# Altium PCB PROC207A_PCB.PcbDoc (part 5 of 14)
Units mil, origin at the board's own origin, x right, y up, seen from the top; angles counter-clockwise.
Board outline 4094.49 x 3724.79 mil, 8 copper layers (Top Layer, L2_GND1, L3_SIG1, L4_PWR1, L5_PWR2, L6_SIG2, L7_GND2, Bottom Layer), stack 58.1 mil thick; 584 components, 399 nets, 8440 pads, 5258 vias.
Unrouted connection lines stored in the file: 9.
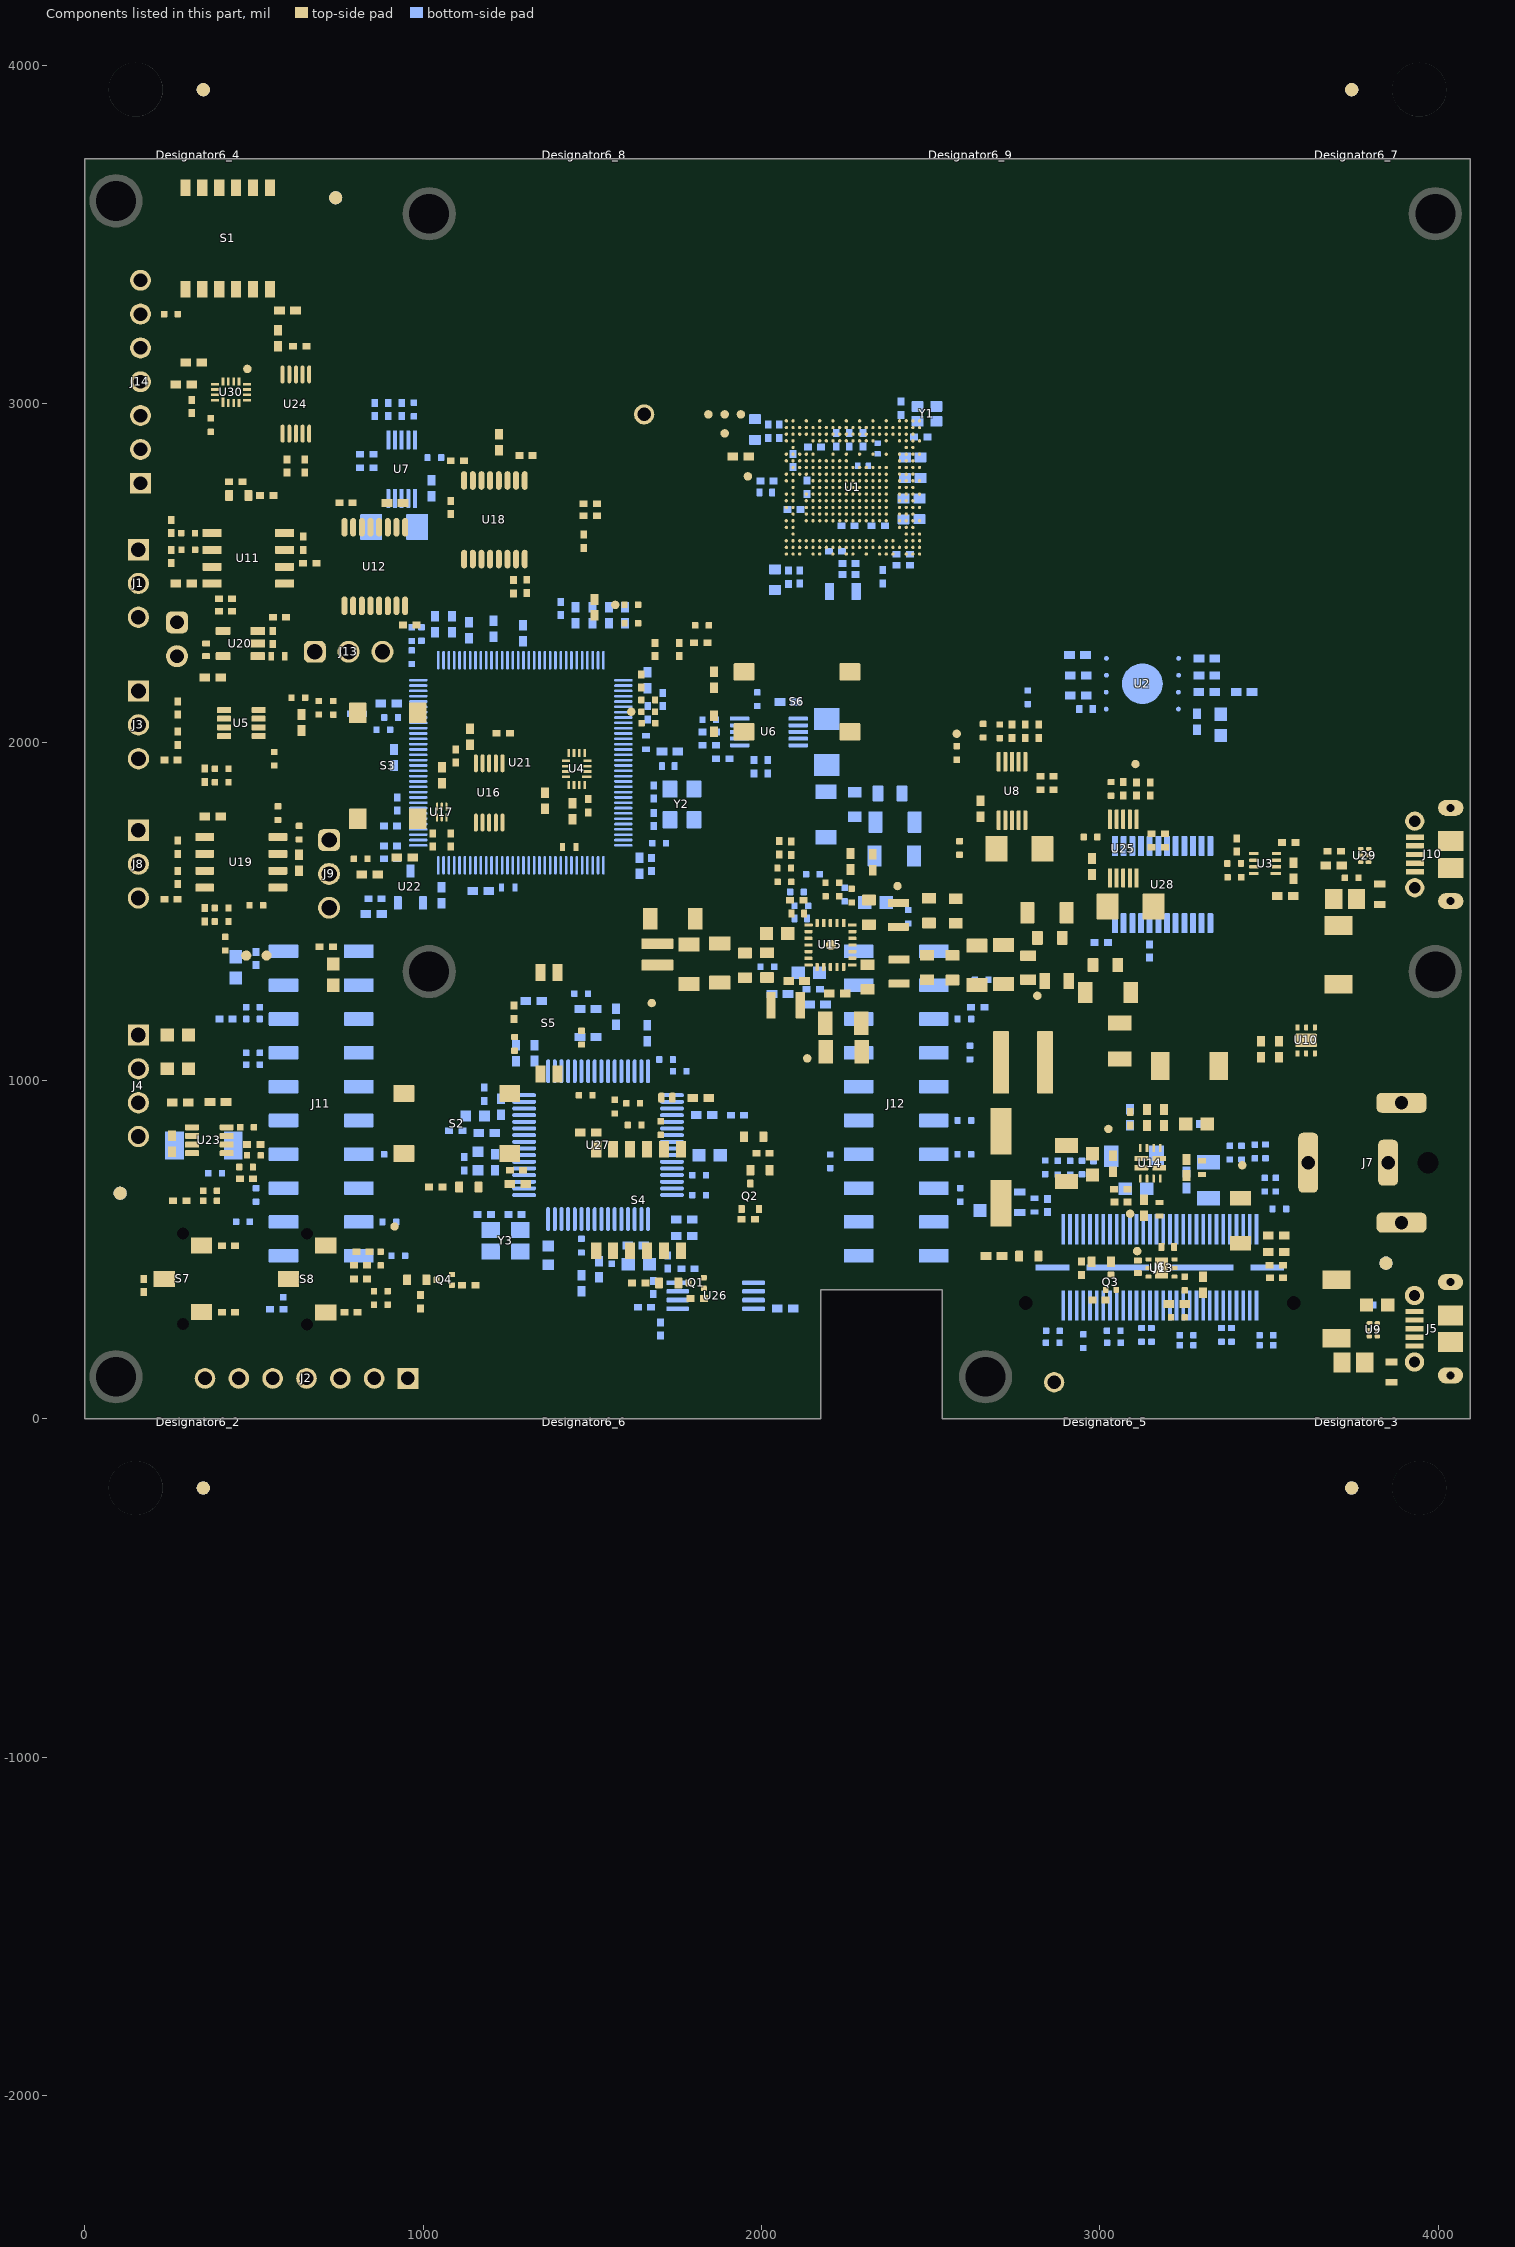
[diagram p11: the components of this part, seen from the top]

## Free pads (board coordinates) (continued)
  round 6 on Mech16: 1(433.25,767.31) 1(433.25,767.31) 1(433.25,798.8) 1(433.25,798.8) 1(437.27,664.31) 1(437.27,664.31) 1(437.27,695.8) 1(437.27,695.8) 1(446.26,465.31) 1(446.26,465.31) 1(446.26,496.8) 1(446.26,496.8) 1(448.26,567.31) 1(448.26,567.31) 1(448.26,598.8) 1(448.26,598.8) 1(453.78,767.31) 1(453.78,798.8) 1(457.79,664.31) 1(457.79,695.8) 1(466.79,465.31) 1(466.79,496.8) 1(468.79,567.31) 1(468.79,598.8) 1(471.78,767.31) 1(471.78,798.8) 1(475.79,664.31) 1(475.79,695.8) 1(478.32,-915.47) 1(479.32,-865.47) 1(481.32,-863.47) 1(481.32,-863.47) 1(481.32,-815.47) 1(481.32,-815.47) 1(484.79,465.31) 1(484.79,496.8) 1(486.79,567.31) 1(486.79,598.8) 1(492.31,767.31) 1(492.31,767.31) 1(492.31,798.8) 1(492.31,798.8) 1(492.32,-915.47) 1(492.32,-915.47) 1(492.32,-804.47) 1(496.32,664.31) 1(496.32,664.31) 1(496.32,695.8) 1(496.32,695.8) 1(505.31,465.31) 1(505.31,465.31) 1(505.31,496.8) 1(505.31,496.8) 1(507.31,567.31) 1(507.31,567.31) 1(507.31,598.8) 1(507.31,598.8) 1(507.32,-900.47) 1(558.04,-34.47) 1(558.04,-34.47) 1(558.04,-13.94) 1(558.04,4.06) 1(558.04,24.59) 1(558.04,24.59) 1(561.32,-56.47) 1(589.53,-34.47) 1(589.53,-34.47) 1(589.53,-13.94) 1(589.53,4.06) 1(589.53,24.59) 1(589.53,24.59) 1(593.32,-56.47) 1(593.32,-56.47) 1(594.32,-55.47) 1(662.41,-202.87) 1(662.41,-202.87) 1(662.41,-182.34) 1(662.41,-164.34) 1(662.41,-143.81) 1(662.41,-143.81) 1(662.41,-132.87) 1(662.41,-132.87) 1(662.41,-112.34) 1(662.41,-94.34) 1(662.41,-73.81) 1(662.41,-73.81) 1(693.9,-202.87) 1(693.9,-202.87) 1(693.9,-182.34) 1(693.9,-164.34) 1(693.9,-143.81) 1(693.9,-143.81) 1(693.9,-132.87) 1(693.9,-132.87) 1(693.9,-112.34) 1(693.9,-94.34) 1(693.9,-73.81) 1(693.9,-73.81) 1(787.16,1515.96) 1(787.16,1515.96) 1(787.16,2008) 1(787.16,2008) 1(794.6,1523.56) 1(794.6,1523.56) 1(794.6,1697.96) 1(794.6,1697.96) 1(794.68,1523.48) 1(794.68,1523.48) 1(794.68,1697.92) 1(794.68,1697.92) 1(833.52,1958.52) 1(833.52,1958.52) 1(835.4,1965.36) 1(835.4,1965.36) 1(835.52,1949.8) 1(835.52,1949.8) 1(835.56,1965.6) 1(835.56,1965.6) 1(835.64,1579.88) 1(835.64,1579.88) 1(835.64,1596.8) 1(835.64,1596.8) 1(837.76,1579.88) 1(837.76,1579.88) 1(837.76,1593.92) 1(837.76,1593.92) 1(837.84,1593.92) 1(837.84,1593.92) 1(838.72,1596.8) 1(838.72,1596.8) 1(839,1957.24) 1(839,1957.24) 1(839.88,1962.4) 1(839.88,1962.4) 1(839.96,1962.56) 1(839.96,1962.56) 1(840.48,1951.8) 1(840.48,1951.8) 1(841.2,1969.8) 1(841.2,1969.8) 1(843.12,1579.88) 1(843.12,1579.88) 1(844.08,1582.56) 1(844.08,1582.56) 1(844.4,1965.2) 1(844.4,1965.2) 1(845,1579.88) 1(845,1579.88) 1(845.16,1943.08) 1(845.16,1943.08) 1(847.48,1930.88) 1(847.48,1930.88) 1(849.4,1596.8) 1(849.4,1596.8) 1(850.04,1965.8) 1(850.04,1965.8) 1(850.08,1971.16) 1(850.08,1971.16) 1(850.32,1593.92) 1(850.32,1593.92) 1(850.36,1579.88) 1(850.36,1579.88) 1(850.36,1593.92) 1(850.36,1593.92) 1(852.48,1579.88) 1(852.48,1579.88) 1(852.48,1596.8) 1(852.48,1596.8) 1(852.52,1933.12) 1(852.52,1933.12) 1(854.36,1594.88) 1(854.36,1594.88) 1(854.36,1596.8) 1(854.36,1596.8) 1(860.04,1579.88) 1(860.04,1579.88) 1(860.04,1594.88) 1(860.04,1594.88) 1(860.04,1964.6) 1(860.04,1964.6) 1(860.16,1970.04) 1(860.16,1970.04) 1(862.24,1922.32) 1(862.24,1922.32) 1(862.28,1579.88) 1(862.28,1579.88) 1(862.28,1594.88) 1(862.28,1594.88) 1(867.92,1594.88) 1(867.92,1594.88) 1(867.92,1596.8) 1(867.92,1596.8) 1(868,1909.28) 1(868,1909.28) 1(868.56,1626.32) 1(868.56,1626.32) 1(868.56,1646.72) 1(868.56,1646.72) 1(869.32,1651.12) 1(869.32,1651.12) 1(870.6,1557.36) 1(870.6,1557.36) 1(870.6,1598.36) 1(870.6,1598.36) 1(871.44,1654.28) 1(871.44,1654.28) 1(872.04,1966.96) 1(872.04,1966.96) 1(872.16,1961.32) 1(872.16,1961.32) 1(874.08,1910.96) 1(874.08,1910.96) 1(874.72,1656.2) 1(874.72,1656.2) 1(875.12,1626.32) 1(875.12,1626.32) 1(875.12,1645) 1(875.12,1645) 1(876.64,1650.08) 1(876.64,1650.08) 1(877.72,1922.28) 1(877.72,1922.28) 1(878.2,1557.36) 1(878.2,1557.36) 1(878.2,1560.6) 1(878.2,1560.6) 1(878.32,1560.6) 1(878.32,1560.6) 1(878.52,1572.8) 1(878.52,1572.8) 1(878.52,1585.4) 1(878.52,1585.4) 1(878.52,1598.36) 1(878.52,1598.36) 1(878.62,-1419.4) 1(878.64,1585.4) 1(878.64,1585.4) 1(878.72,1568.4) 1(878.72,1568.4) 1(878.72,1577.24) 1(878.72,1577.24) 1(879.12,1656.84) 1(879.12,1656.84) 1(879.32,1565.2) 1(879.32,1565.2) 1(879.32,1580.4) 1(879.32,1580.4) 1(880.6,1563.28) 1(880.6,1563.28) 1(880.6,1582.32) 1(880.6,1582.32) 1(880.92,1651.68) 1(880.92,1651.68) 1(881.32,1557.52) 1(881.32,1557.52) 1(881.48,1588.16) 1(881.48,1588.16) 1(882.76,1562.64) 1(882.76,1562.64) 1(882.76,1582.96) 1(882.76,1582.96) 1(883.92,1651.08) 1(883.92,1651.08) 1(884.12,1933.44) 1(884.12,1933.44) 1(884.4,1655.52) 1(884.4,1655.52) 1(884.84,1563.28) 1(884.84,1563.28) 1(884.84,1582.32) 1(884.84,1582.32) 1(885.32,1556.52) 1(885.32,1556.52) 1(885.32,1589.04) 1(885.32,1589.04) 1(885.36,1962.16) 1(885.36,1962.16) 1(886,1956.12) 1(886,1956.12) 1(886.12,1565.2) 1(886.12,1565.2) 1(886.12,1580.4) 1(886.12,1580.4) 1(886.16,1649.4) 1(886.16,1649.4) 1(886.72,1568.36) 1(886.72,1568.36) 1(886.72,1577.24) 1(886.72,1577.24) 1(886.88,1572.8) 1(886.88,1572.8) 1(887.6,1646.92) 1(887.6,1646.92) 1(887.79,-1434) 1(887.79,-1428.57) 1(887.79,-1428.57) 1(888,1652.12) 1(888,1652.12) 1(888.12,1626.32) 1(888.12,1626.32) 1(888.12,1643.84) 1(888.12,1643.84) 1(888.12,1652.12) 1(888.12,1652.12) 1(888.12,1667.36) 1(888.12,1667.36) 1(889.56,1557.44) 1(889.56,1557.44) 1(889.56,1588.12) 1(889.56,1588.12) 1(892.28,1942.92) 1(892.28,1942.92) 1(892.52,1560.36) 1(892.52,1560.36) 1(892.52,1585.24) 1(892.52,1585.24) 1(894.24,1565.4) 1(894.24,1565.4) 1(894.24,1580.2) 1(894.24,1580.2) 1(894.32,1887.44) 1(894.32,1887.44) 1(894.68,1626.32) 1(894.68,1626.32) 1(894.68,1667.36) 1(894.68,1667.36) 1(894.8,1572.8) 1(894.8,1572.8) 1(899.32,1557.36) 1(899.32,1557.36) 1(899.68,1955.8) 1(899.68,1955.8) 1(899.92,1626.36) 1(899.92,1626.36) 1(899.92,1631.44) 1(899.92,1631.44) 1(899.92,1651.16) 1(899.92,1651.16) 1(899.92,1656.04) 1(899.92,1656.04) 1(900.08,1559.92) 1(900.08,1559.92) 1(900.28,1563.32) 1(900.28,1563.32) 1(900.28,1579.6) 1(900.28,1579.6) 1(900.68,1583.4) 1(900.68,1583.4) 1(901.12,1949.16) 1(901.12,1949.16) 1(902.36,1586.4) 1(902.36,1586.4) 1(902.68,1631.2) 1(902.68,1631.2) 1(904.16,1626.04) 1(904.16,1626.04) 1(905.36,1632.24) 1(905.36,1632.24) 1(905.76,1588.36) 1(905.76,1588.36) 1(905.84,1635.28) 1(905.84,1635.28) 1(905.84,1651.16) 1(905.84,1651.16) 1(905.84,1656.04) 1(905.84,1656.04) 1(905.84,1664.96) 1(905.84,1664.96) 1(906.88,1557.36) 1(906.88,1557.36) 1(907.88,1560.56) 1(907.88,1560.56) 1(907.88,1566.72) 1(907.88,1566.72) 1(907.88,1572.8) 1(907.88,1572.8) 1(907.88,1579.88) 1(907.88,1579.88) 1(907.96,1560.56) 1(907.96,1560.56) 1(908.32,1626.52) 1(908.32,1626.52) 1(908.56,1577.52) 1(908.56,1577.52) 1(908.72,1582.64) 1(908.72,1582.64) 1(909.52,1563.04) 1(909.52,1563.04) 1(910.8,1628) 1(910.8,1628) 1(910.96,1882.16) 1(910.96,1882.16) 1(911,1576.24) 1(911,1576.24) 1(911.16,1557.36) 1(911.16,1557.36) 1(911.24,1571.24) 1(911.24,1571.24) 1(911.48,1589.04) 1(911.48,1589.04) 1(911.52,1583.64) 1(911.52,1583.64) 1(912,1630.36) 1(912,1630.36) 1(912.36,1633.64) 1(912.36,1633.64) 1(912.36,1651.16) 1(912.36,1651.16) 1(912.36,1656.04) 1(912.36,1656.04) 1(912.36,1664.96) 1(912.36,1664.96) 1(912.76,1561.92) 1(912.76,1561.92) 1(914.28,1582.56) 1(914.28,1582.56) 1(914.28,1895.2) 1(914.28,1895.2) 1(914.56,1948.12) 1(914.56,1948.12) 1(914.72,1569.52) 1(914.72,1569.52) 1(915.04,1563.2) 1(915.04,1563.2) 1(915.2,1578.8) 1(915.2,1578.8) 1(915.2,1579.64) 1(915.2,1579.64) 1(915.52,1575.04) 1(915.52,1575.04) 1(915.72,1566.24) 1(915.72,1566.24) 1(915.72,1588.56) 1(915.72,1588.56) 1(915.84,1556.52) 1(915.84,1556.52) 1(917.32,1651.16) 1(917.32,1651.16) 1(917.32,1656.04) 1(917.32,1656.04) 1(919.04,1573.72) 1(919.04,1573.72) 1(919.16,1586.96) 1(919.16,1586.96) 1(919.36,1557.32) 1(919.36,1557.32) 1(921.44,1571.84) 1(921.44,1571.84) 1(921.48,1584.04) 1(921.48,1584.04) 1(921.64,1559.4) 1(921.64,1559.4) 1(921.64,1908.32) 1(921.64,1908.32) 1(921.96,1626.32) 1(921.96,1626.32) 1(921.96,1656.04) 1(921.96,1656.04) 1(921.96,1661.16) 1(921.96,1661.16) 1(921.96,1667.36) 1(921.96,1667.36) 1(922.32,1578.8) 1(922.32,1578.8) 1(922.32,1579.52) 1(922.32,1579.52) 1(922.88,1569.12) 1(922.88,1569.12) 1(922.92,1562.28) 1(922.92,1562.28) 1(923.32,-48.23) 1(923.32,-48.23) 1(923.32,-39.47) 1(923.32,1565.4) 1(923.32,1565.4) 1(923.64,1867.84) 1(923.64,1867.84) 1(924.24,1586.08) 1(924.24,1586.08) 1(924.84,1590.6) 1(924.84,1590.6) 1(925.2,1580.56) 1(925.2,1580.56) 1(926.72,1594.52) 1(926.72,1594.52) 1(927.68,1865.48) 1(927.68,1865.48) 1(927.84,1576.72) 1(927.84,1576.72) 1(928.52,1626.32) 1(928.52,1626.32) 1(928.52,1656.04) 1(928.52,1656.04) 1(928.52,1661.16) 1(928.52,1661.16) 1(928.52,1667.36) 1(928.52,1667.36) 1(929.64,1939.36) 1(929.64,1939.36) 1(930.2,1597.32) 1(930.2,1597.32) 1(930.41,-55.32) 1(930.56,1846.16) 1(930.56,1846.16) 1(931.36,1919.08) 1(931.36,1919.08) 1(931.96,1574.48) 1(931.96,1574.48) 1(932.52,1585.96) 1(932.52,1585.96) 1(933.44,1656.04) 1(933.44,1656.04) 1(933.52,1892.56) 1(933.52,1892.56) 1(933.84,1590.64) 1(933.84,1590.64) 1(934.04,1581.32) 1(934.04,1581.32) 1(934.68,1846.84) 1(934.68,1846.84) 1(935.4,651.01) 1(935.4,651.01) 1(935.4,651.01) 1(935.52,1598.36) 1(935.52,1598.36) 1(937.28,1573.72) 1(937.28,1573.72) 1(938.04,1579.8) 1(938.04,1579.8) 1(938.28,1592.28) 1(938.28,1592.28) 1(939.32,1901.08) 1(939.32,1901.08) 1(940.08,1656.04) 1(940.08,1656.04) 1(941.08,1925.6) 1(941.08,1925.6) 1(941.72,1557.36) 1(941.72,1557.36) 1(941.72,1573.72) 1(941.72,1573.72) 1(941.72,1579.8) 1(941.72,1579.8) 1(941.72,1592.28) 1(941.72,1592.28) 1(941.76,1925.04) 1(941.76,1925.04) 1(942.72,1626.32) 1(942.72,1626.32) 1(943.72,1863) 1(943.72,1863) 1(943.9,642.51) 1(943.9,642.51) 1(943.9,659.51) 1(943.9,659.51) 1(944.44,1929.68) 1(944.44,1929.68) 1(945.96,1828.64) 1(945.96,1828.64) 1(946.12,1633.84) 1(946.12,1633.84) 1(946.24,1633.84) 1(946.24,1633.84) 1(946.42,-1436) 1(946.42,-1425) 1(946.42,-1425) 1(946.42,-1425) 1(949.32,1854.56) 1(949.32,1854.56) 1(949.44,1626.32) 1(949.44,1626.32) 1(950,1557.36) 1(950,1557.36) 1(950,1598.36) 1(950,1598.36) 1(951.24,1829.24) 1(951.24,1829.24) 1(951.6,1656.04) 1(951.6,1656.04) 1(954.96,1648.4) 1(954.96,1648.4) 1(955.08,1648.4) 1(955.08,1648.4) 1(957.2,1557.36) 1(957.2,1557.36) 1(957.2,1580.28) 1(957.2,1580.28) 1(957.72,1584.2) 1(957.72,1584.2) 1(958.2,1656.04) 1(958.2,1656.04) 1(958.64,1919.32) 1(958.64,1919.32) 1(959.28,1586.96) 1(959.28,1586.96) 1(960.56,1626.32) 1(960.56,1626.32) 1(961.76,1588.56) 1(961.76,1588.56) 1(962.32,1916.44) 1(962.32,1916.44) 1(963.44,1820.72) 1(963.44,1820.72) 1(963.76,1633.84) 1(963.76,1633.84) 1(963.88,1633.84) 1(963.88,1633.84) 1(965.08,1589.04) 1(965.08,1589.04) 1(965.12,1557.36) 1(965.12,1557.36) 1(965.12,1578.64) 1(965.12,1578.64) 1(965.2,1815.24) 1(965.2,1815.24) 1(965.36,1834.68) 1(965.36,1834.68) 1(965.92,1581.96) 1(965.92,1581.96) 1(966.16,1840.92) 1(966.16,1840.92) 1(966.6,1828.96) 1(966.6,1828.96) 1(967.44,1626.32) 1(967.44,1626.32) 1(968.52,1582.96) 1(968.52,1582.96) 1(969.2,1834.84) 1(969.2,1834.84) 1(969.24,1824.2) 1(969.24,1824.2) 1(969.52,1588.08) 1(969.52,1588.08) 1(969.68,1656.04) 1(969.68,1656.04) 1(969.72,1847.16) 1(969.72,1847.16) 1(969.76,1847.2) 1(969.76,1847.2) 1(969.84,1839.8) 1(969.84,1839.8) 1(969.96,1921.52) 1(969.96,1921.52) 1(970.2,1830.28) 1(970.2,1830.28) 1(970.68,1822.24) 1(970.68,1822.24) 1(970.72,1902.32) 1(970.72,1902.32) 1(971.64,1581.72) 1(971.64,1581.72) 1(972.28,1826.48) 1(972.28,1826.48) 1(972.6,1585.12) 1(972.6,1585.12) 1(972.68,1844.72) 1(972.68,1844.72) 1(972.72,1557.36) 1(972.72,1557.36) 1(972.72,1577.84) 1(972.72,1577.84) 1(972.72,1585.12) 1(972.72,1585.12) 1(972.72,1598.36) 1(972.72,1598.36) 1(972.8,1844.88) 1(972.8,1844.88) 1(972.96,1851.92) 1(972.96,1851.92) 1(973.76,1818.04) 1(973.76,1818.04) 1(973.76,1824.48) 1(973.76,1824.48) 1(976.64,1656.04) 1(976.64,1656.04) 1(977.64,1812.96) 1(977.64,1812.96) 1(979.04,1817.4) 1(979.04,1817.4) 1(980,1862.24) 1(980,1862.24) 1(980.48,1900.36) 1(980.48,1900.36) 1(980.64,1557.36) 1(980.64,1557.36) 1(980.64,1598.36) 1(980.64,1598.36) 1(981.36,1920.88) 1(981.36,1920.88) 1(982.24,1916.76) 1(982.24,1916.76) 1(983.2,1860.16) 1(983.2,1860.16) 1(983.64,1805.96) 1(983.64,1805.96) 1(984.6,1869.04) 1(984.6,1869.04) 1(985.32,1569.16) 1(985.32,1569.16) 1(985.32,1577.12) 1(985.32,1577.12) 1(985.84,1809) 1(985.84,1809) 1(985.96,1563.8) 1(985.96,1563.8) 1(986,1582.04) 1(986,1582.04) 1(987.72,1866.8) 1(987.72,1866.8) 1(988.04,1559.8) 1(988.04,1559.8) 1(988.12,1585.8) 1(988.12,1585.8) 1(988.4,1837.72) 1(988.4,1837.72) 1(991.52,1839.92) 1(991.52,1839.92) 1(991.56,1588.2) 1(991.56,1588.2) 1(991.56,1879.32) 1(991.56,1879.32) 1(991.68,1557.36) 1(991.68,1557.36) 1(992.52,1917.84) 1(992.52,1917.84) 1(992.88,1569.16) 1(992.88,1569.16) 1(992.88,1577.12) 1(992.88,1577.12) 1(993.56,1581.32) 1(993.56,1581.32) 1(993.8,1563.68) 1(993.8,1563.68) 1(994.8,1884) 1(994.8,1884) 1(994.84,1884.04) 1(994.84,1884.04) 1(995.96,1635.16) 1(995.96,1635.16) 1(996.36,1589.04) 1(996.36,1589.04) 1(996.44,1583.32) 1(996.44,1583.32) 1(996.72,1561.92) 1(996.72,1561.92) 1(996.8,1638.84) 1(996.8,1638.84) 1(996.96,1647.72) 1(996.96,1647.72) 1(997.08,1556.52) 1(997.08,1556.52) 1(997.2,1630.68) 1(997.2,1630.68) 1(998.16,1882.2) 1(998.16,1882.2) 1(998.36,1651.92) 1(998.36,1651.92) 1(998.8,1582.68) 1(998.8,1582.68) 1(998.92,1562.56) 1(998.92,1562.56) 1(999,1641.32) 1(999,1641.32) 1(999.32,1889.68) 1(999.32,1889.68) 1(1000.2,1564.48) 1(1000.2,1564.48) 1(1000.2,1580.72) 1(1000.2,1580.72) 1(1000.28,1627.72) 1(1000.28,1627.72) 1(1000.84,1567.84) 1(1000.84,1567.84) 1(1000.84,1577.4) 1(1000.84,1577.4) 1(1001,1572.72) 1(1001,1572.72) 1(1001.16,1654.76) 1(1001.16,1654.76) 1(1001.44,1588.32) 1(1001.44,1588.32) 1(1001.72,1886.68) 1(1001.72,1886.68) 1(1002.04,1642.88) 1(1002.04,1642.88) 1(1002.28,1557.32) 1(1002.28,1557.32) 1(1002.52,1634.6) 1(1002.52,1634.6) 1(1003.12,1632.56) 1(1003.12,1632.56) 1(1003.32,1913) 1(1003.32,1913) 1(1003.44,1636.68) 1(1003.44,1636.68) 1(1003.76,1647.72) 1(1003.76,1647.72) 1(1003.84,1862.88) 1(1003.84,1862.88) 1(1004.08,1862.76) 1(1004.08,1862.76) 1(1004.6,1626.04) 1(1004.6,1626.04) 1(1004.68,1907.84) 1(1004.68,1907.84) 1(1004.8,1892.72) 1(1004.8,1892.72) 1(1004.84,1631.4) 1(1004.84,1631.4) 1(1004.96,1656.36) 1(1004.96,1656.36) 1(1005.28,1821.6) 1(1005.28,1821.6) 1(1005.36,1866.36) 1(1005.36,1866.36) 1(1005.4,1585.68) 1(1005.4,1585.68) 1(1005.56,1643.84) 1(1005.56,1643.84) 1(1005.56,1866.28) 1(1005.56,1866.28) 1(1005.64,1637.96) 1(1005.64,1637.96) 1(1005.92,1650.84) 1(1005.92,1650.84) 1(1005.96,1560) 1(1005.96,1560) 1(1006.08,1889.08) 1(1006.08,1889.08) 1(1007.04,1630.84) 1(1007.04,1630.84) 1(1008,1580.68) 1(1008,1580.68) 1(1008.2,1565.04) 1(1008.2,1565.04) 1(1008.72,1638.8) 1(1008.72,1638.8) 1(1008.92,1572.8) 1(1008.92,1572.8) 1(1009.12,1630.68) 1(1009.12,1630.68) 1(1009.12,1644.6) 1(1009.12,1644.6) 1(1009.24,1625.52) 1(1009.24,1625.52) 1(1009.36,1656.84) 1(1009.36,1656.84) 1(1009.8,1651.68) 1(1009.8,1651.68) 1(1009.88,1842.8) 1(1009.88,1842.8) 1(1010.6,1893.64) 1(1010.6,1893.64) 1(1010.72,1889.84) 1(1010.72,1889.84) 1(1012.2,1645.44) 1(1012.2,1645.44) 1(1012.24,1639.56) 1(1012.24,1639.56) 1(1012.92,1835.4) 1(1012.92,1835.4) 1(1013.24,1651.12) 1(1013.24,1651.12) 1(1013.48,1906.88) 1(1013.48,1906.88) 1(1013.56,1656.44) 1(1013.56,1656.44) 1(1013.6,1557.36) 1(1013.6,1557.36) 1(1013.6,1580.28) 1(1013.6,1580.28) 1(1013.68,1631.84) 1(1013.68,1631.84) 1(1013.72,1848.4) 1(1013.72,1848.4) 1(1014.12,1584.2) 1(1014.12,1584.2) 1(1014.4,1646.68) 1(1014.4,1646.68) 1(1014.44,1626.16) 1(1014.44,1626.16) 1(1015,1889.24) 1(1015,1889.24) 1(1015.2,1648.64) 1(1015.2,1648.64) 1(1015.68,1586.96) 1(1015.68,1586.96) 1(1015.76,1640.52) 1(1015.76,1640.52) 1(1015.84,1635.84) 1(1015.84,1635.84) 1(1015.84,1635.88) 1(1015.84,1635.88) 1(1015.92,1837.76) 1(1015.92,1837.76) 1(1016,1892.96) 1(1016,1892.96) 1(1016.52,1802.72) 1(1016.52,1802.72) 1(1017.08,1899.64) 1(1017.08,1899.64) 1(1017.36,1857) 1(1017.36,1857) 1(1017.4,1888.64) 1(1017.4,1888.64) 1(1017.6,1655.04) 1(1017.6,1655.04) 1(1018.12,1588.56) 1(1018.12,1588.56) 1(1018.36,1892.36) 1(1018.36,1892.36) 1(1018.6,1628.08) 1(1018.6,1628.08) 1(1018.8,1642.08) 1(1018.8,1642.08) 1(1018.96,1860.48) 1(1018.96,1860.48) 1(1019.48,1805.32) 1(1019.48,1805.32) 1(1020.6,1652.4) 1(1020.6,1652.4) 1(1020.96,1644.56) 1(1020.96,1644.56) 1(1021.36,1631.28) 1(1021.36,1631.28) 1(1021.44,1589.04) 1(1021.44,1589.04) 1(1021.52,1557.36) 1(1021.52,1557.36) 1(1021.52,1578.64) 1(1021.52,1578.64) 1(1021.76,1648.32) 1(1021.76,1648.32) 1(1022.32,1581.96) 1(1022.32,1581.96) 1(1022.44,1635.88) 1(1022.44,1635.88) 1(1022.84,1900.04) 1(1022.84,1900.04) 1(1023.4,1891) 1(1023.4,1891) 1(1024.52,1626.32) 1(1024.52,1626.32) 1(1024.92,1582.96) 1(1024.92,1582.96) 1(1025.64,1656.04) 1(1025.64,1656.04) 1(1025.92,1886.32) 1(1025.92,1886.32) 1(1026,1588) 1(1026,1588) 1(1028,1581.72) 1(1028,1581.72) 1(1029.12,1557.36) 1(1029.12,1557.36) 1(1029.12,1577.84) 1(1029.12,1577.84) 1(1029.32,1584.64) 1(1029.32,1584.64) 1(1029.44,1584.64) 1(1029.44,1584.64) 1(1029.44,1588.24) 1(1029.44,1588.24) 1(1029.44,1817) 1(1029.44,1817) 1(1029.52,1889.28) 1(1029.52,1889.28) 1(1031.16,1892.96) 1(1031.16,1892.96) 1(1032.16,1819.72) 1(1032.16,1819.72) 1(1032.4,1850.04) 1(1032.4,1850.04) 1(1032.52,1626.32) 1(1032.52,1626.32) 1(1032.64,1864.12) 1(1032.64,1864.12) 1(1033.32,1867.84) 1(1033.32,1867.84) 1(1033.68,1656.04) 1(1033.68,1656.04) 1(1034.16,1853.44) 1(1034.16,1853.44) 1(1034.44,1790.88) 1(1034.44,1790.88) 1(1036.24,1883.08) 1(1036.24,1883.08) 1(1037,1645.12) 1(1037,1645.12) 1(1037.04,1557.36) 1(1037.04,1557.36) 1(1037.04,1588.24) 1(1037.04,1588.24) 1(1038.2,1886.28) 1(1038.2,1886.28) 1(1041.6,1640.76) 1(1041.6,1640.76) 1(1042.84,1557.36) 1(1042.84,1557.36) 1(1042.84,1588.24) 1(1042.84,1588.24) 1(1045.52,1626.32) 1(1045.52,1626.32) 1(1045.52,1636.96) 1(1045.52,1636.96) 1(1045.52,1644.04) 1(1045.52,1644.04) 1(1045.52,1667.36) 1(1045.52,1667.36) 1(1046.44,1776.08) 1(1046.44,1776.08) 1(1048.36,1800.72) 1(1048.36,1800.72) 1(1048.88,1841.56) 1(1048.88,1841.56) 1(1050.4,1557.36) 1(1050.4,1557.36) 1(1050.4,1560.96) 1(1050.4,1560.96) 1(1050.4,1778.04) 1(1050.4,1778.04) 1(1050.52,1560.96) 1(1050.52,1560.96) 1(1050.6,1858.96) 1(1050.6,1858.96) 1(1050.76,1567.72) 1(1050.76,1567.72) 1(1050.76,1588.24) 1(1050.76,1588.24) 1(1050.76,1803.72) 1(1050.76,1803.72) 1(1050.8,1844.88) 1(1050.8,1844.88) 1(1051.76,1862.6) 1(1051.76,1862.6) 1(1051.84,1563.88) 1(1051.84,1563.88) 1(1052.04,1667.36) 1(1052.04,1667.36) 1(1052.08,1626.32) 1(1052.08,1626.32) 1(1052.08,1667.36) 1(1052.08,1667.36) 1(1053.84,1557.6) 1(1053.84,1557.6) 1(1054.96,1562.64) 1(1054.96,1562.64) 1(1055.64,1650.36) 1(1055.64,1650.36) 1(1055.64,1656.68) 1(1055.64,1656.68) 1(1057.44,651.01) 1(1057.56,1563.64) 1(1057.56,1563.64) 1(1058.08,1656.84) 1(1058.08,1656.84) 1(1058.36,1566.92) 1(1058.36,1566.92) 1(1058.36,1588.24) 1(1058.36,1588.24) 1(1058.4,1556.52) 1(1058.4,1556.52) 1(1058.44,1650.64) 1(1058.44,1650.64) 1(1061.08,1656.28) 1(1061.08,1656.28) 1(1061.6,1649.96) 1(1061.6,1649.96) 1(1061.72,1557.04) 1(1061.72,1557.04) 1(1063.68,1654.76) 1(1063.68,1654.76) 1(1064.16,1648) 1(1064.16,1648) 1(1064.2,1558.64) 1(1064.2,1558.64) 1(1064.4,1764.08) 1(1064.4,1764.08) 1(1065.68,1652.64) 1(1065.68,1652.64) 1(1065.76,1561.4) 1(1065.76,1561.4) 1(1065.88,1644.84) 1(1065.88,1644.84) 1(1066.28,1565.32) 1(1066.28,1565.32) 1(1066.28,1588.24) 1(1066.28,1588.24) 1(1066.48,1626.32) 1(1066.48,1626.32) 1(1066.48,1640.48) 1(1066.48,1640.48) 1(1066.52,1831.28) 1(1066.52,1831.28) 1(1066.8,1650.28) 1(1066.8,1650.28) 1(1066.88,1650.28) 1(1066.88,1650.28) 1(1066.88,1656.04) 1(1066.88,1656.04) 1(1067.68,1766.64) 1(1067.68,1766.64) 1(1068.6,1834.48) 1(1068.6,1834.48) 1(1070.36,1849.96) 1(1070.36,1849.96) 1(1070.52,1785.92) 1(1070.52,1785.92) 1(1071.52,1557.36) 1(1071.52,1557.36) 1(1071.92,1853.44) 1(1071.92,1853.44) 1(1072.32,1559.92) 1(1072.32,1559.92) 1(1072.48,1563.32) 1(1072.48,1563.32) 1(1072.48,1579.6) 1(1072.48,1579.6) 1(1072.56,1789.16) 1(1072.56,1789.16) 1(1072.92,1583.4) 1(1072.92,1583.4) 1(1073.04,1626.32) 1(1073.04,1626.32) 1(1073.04,1656.04) 1(1073.04,1656.04) 1(1074.56,1586.4) 1(1074.56,1586.4) 1(1078,1588.36) 1(1078,1588.36) 1(1079.12,1557.36) 1(1079.12,1557.36) 1(1079.12,1641.2) 1(1079.12,1641.2) 1(1080.08,1560.56) 1(1080.08,1560.56) 1(1080.08,1566.72) 1(1080.08,1566.72) 1(1080.08,1572.8) 1(1080.08,1572.8) 1(1080.08,1579.88) 1(1080.08,1579.88) 1(1080.12,1634.92) 1(1080.12,1634.92) 1(1080.12,1647.48) 1(1080.12,1647.48) 1(1080.2,1560.56) 1(1080.2,1560.56) 1(1080.8,1577.52) 1(1080.8,1577.52) 1(1080.92,1582.64) 1(1080.92,1582.64) 1(1081.72,1563.04) 1(1081.72,1563.04) 1(1083.04,1629.92) 1(1083.04,1629.92) 1(1083.04,1652.44) 1(1083.04,1652.44) 1(1083.24,1576.24) 1(1083.24,1576.24) 1(1083.4,1557.36) 1(1083.4,1557.36) 1(1083.48,1571.24) 1(1083.48,1571.24) 1(1083.72,1589.04) 1(1083.72,1589.04) 1(1083.76,1583.64) 1(1083.76,1583.64) 1(1084.4,1753.2) 1(1084.4,1753.2) 1(1084.96,1561.92) 1(1084.96,1561.92) 1(1085,1818.88) 1(1085,1818.88) 1(1085.64,1641.2) 1(1085.64,1641.2) 1(1086.12,1637.4) 1(1086.12,1637.4) 1(1086.12,1645) 1(1086.12,1645) 1(1086.52,1582.56) 1(1086.52,1582.56) 1(1086.6,1756.36) 1(1086.6,1756.36) 1(1086.92,1569.52) 1(1086.92,1569.52) 1(1087.28,1563.2) 1(1087.28,1563.2) 1(1087.28,1821.96) 1(1087.28,1821.96) 1(1087.44,1578.8) 1(1087.44,1578.8) 1(1087.44,1579.64) 1(1087.44,1579.64) 1(1087.68,1634) 1(1087.68,1634) 1(1087.68,1648.36) 1(1087.68,1648.36) 1(1087.72,1575.04) 1(1087.72,1575.04) 1(1087.72,1626.68) 1(1087.72,1626.68) 1(1087.72,1655.68) 1(1087.72,1655.68) 1(1087.92,1588.56) 1(1087.92,1588.56) 1(1087.96,1566.24) 1(1087.96,1566.24) 1(1088.08,1556.52) 1(1088.08,1556.52) 1(1090.28,1631.6) 1(1090.28,1631.6) 1(1090.28,1650.76) 1(1090.28,1650.76) 1(1091.2,1837.56) 1(1091.2,1837.56) 1(1091.24,1573.72) 1(1091.24,1573.72) 1(1091.4,1586.96) 1(1091.4,1586.96) 1(1091.6,1557.32) 1(1091.6,1557.32) 1(1093.2,1840.8) 1(1093.2,1840.8) 1(1093.68,1571.84) 1(1093.68,1571.84) 1(1093.72,1584.04) 1(1093.72,1584.04) 1(1093.88,1559.4) 1(1093.88,1559.4) 1(1094.08,1625.52) 1(1094.08,1625.52) 1(1094.08,1630.68) 1(1094.08,1630.68) 1(1094.08,1651.68) 1(1094.08,1651.68) 1(1094.08,1656.84) 1(1094.08,1656.84) 1(1094.56,1578.8) 1(1094.56,1578.8) 1(1094.56,1579.52) 1(1094.56,1579.52) 1(1095.08,1569.12) 1(1095.08,1569.12) 1(1095.16,1562.28) 1(1095.16,1562.28) 1(1095.56,1565.4) 1(1095.56,1565.4) 1(1096.64,1772) 1(1096.64,1772) 1(1097.88,1631.6) 1(1097.88,1631.6) 1(1097.88,1650.76) 1(1097.88,1650.76) 1(1098.32,1775.44) 1(1098.32,1775.44) 1(1098.48,1557.36) 1(1098.48,1557.36) 1(1098.48,1564.12) 1(1098.48,1564.12) 1(1100.44,1626.68) 1(1100.44,1626.68) 1(1100.44,1655.68) 1(1100.44,1655.68) 1(1100.52,1634) 1(1100.52,1634) 1(1100.52,1648.36) 1(1100.52,1648.36) 1(1102.04,1637.4) 1(1102.04,1637.4) 1(1102.04,1645) 1(1102.04,1645) 1(1102.56,1641.2) 1(1102.56,1641.2) 1(1104.04,1804.04) 1(1104.04,1804.04) 1(1105.16,1629.92) 1(1105.16,1629.92) 1(1105.16,1652.44) 1(1105.16,1652.44) 1(1106.52,1806.96) 1(1106.52,1806.96) 1(1106.84,1743.24) 1(1106.84,1743.24) 1(1107.48,1747.12) 1(1107.48,1747.12) 1(1108.08,1634.92) 1(1108.08,1634.92) 1(1108.08,1647.48) 1(1108.08,1647.48) 1(1109.08,1641.2) 1(1109.08,1641.2) 1(1111.12,1667.36) 1(1111.12,1667.36) 1(1112.44,1822.04) 1(1112.44,1822.04) 1(1113.12,1564.12) 1(1113.12,1564.12) 1(1113.12,1598.36) 1(1113.12,1598.36) 1(1114.84,1825.04) 1(1114.84,1825.04) 1(1118.4,1667.36) 1(1118.4,1667.36) 1(1121.4,1557.36) 1(1121.4,1557.36) 1(1121.4,1598.36) 1(1121.4,1598.36) 1(1122.44,1626.32) 1(1122.44,1626.32) 1(1122.76,1756.84) 1(1122.76,1756.84) 1(1123.28,1786.48) 1(1123.28,1786.48) 1(1125.44,1759.48) 1(1125.44,1759.48) 1(1125.96,1789.2) 1(1125.96,1789.2) 1(1126.04,1635.96) 1(1126.04,1635.96) 1(1126.16,1635.96) 1(1126.16,1635.96) 1(1128.16,1746.72) 1(1128.16,1746.72) 1(1129.56,1752.68) 1(1129.56,1752.68) 1(1129.72,1626.32) 1(1129.72,1626.32) 1(1130.56,1738.6) 1(1130.56,1738.6) 1(1132.04,1734.08) 1(1132.04,1734.08) 1(1133.12,1744.4) 1(1133.12,1744.4) 1(1134.2,1667.36) 1(1134.2,1667.36) 1(1134.24,1803.04) 1(1134.24,1803.04) 1(1134.56,1735.88) 1(1134.56,1735.88) 1(1134.6,1733.24) 1(1134.6,1733.24) 1(1137.72,1804.96) 1(1137.72,1804.96) 1(1137.96,1657.68) 1(1137.96,1657.68) 1(1138.08,1657.68) 1(1138.08,1657.68) 1(1140.2,1751.76) 1(1140.2,1751.76) 1(1141.56,1667.36) 1(1141.56,1667.36) 1(1142.4,1557.36) 1(1142.4,1557.36) 1(1142.4,1598.36) 1(1142.4,1598.36) 1(1142.48,1765.84) 1(1142.48,1765.84) 1(1145.2,1745.56) 1(1145.2,1745.56) 1(1145.4,1768.32) 1(1145.4,1768.32) 1(1146.44,1626.32) 1(1146.44,1626.32) 1(1149.84,1635.96) 1(1149.84,1635.96) 1(1149.96,1635.96) 1(1149.96,1635.96) 1(1150.68,1557.36) 1(1150.68,1557.36) 1(1150.68,1598.36) 1(1150.68,1598.36) 1(1153.88,1626.32) 1(1153.88,1626.32) 1(1154.08,1782.24) 1(1154.08,1782.24) 1(1155.16,1591.6) 1(1155.16,1591.6) 1(1155.16,1598.36) 1(1155.16,1598.36) 1(1156.4,1745.56) 1(1156.4,1745.56) 1(1157.36,1667.36) 1(1157.36,1667.36) 1(1158.48,1783) 1(1158.48,1783) 1(1161.52,1739.92) 1(1161.52,1739.92) 1(1164.12,1557.36) 1(1164.12,1557.36) 1(1164.12,1591.6) 1(1164.12,1591.6) 1(1164.68,1667.36) 1(1164.68,1667.36) 1(1171.52,1760.24) 1(1171.52,1760.24) 1(1172.32,1740.84) 1(1172.32,1740.84) 1(1172.4,1557.36) 1(1172.4,1557.36) 1(1172.4,1591.6) 1(1172.4,1591.6) 1(1176.56,1759.72) 1(1176.56,1759.72) 1(1176.84,1735.72) 1(1176.84,1735.72) 1(1181.36,1591.6) 1(1181.36,1591.6) 1(1181.36,1598.36) 1(1181.36,1598.36) 1(1182.76,1114) 1(1182.76,1114) 1(1186.2,1737.44) 1(1186.2,1737.44) 1(1189.56,1001.53) 1(1189.56,1120.8) 1(1189.56,1120.8) 1(1189.56,1732.84) 1(1189.56,1732.84) 1(1189.69,1120.8) 1(1191.6,1735.64) 1(1191.6,1735.64) 1(1193.6,1732) 1(1193.6,1732) 1(1196.49,1114) 1(1196.49,1114) 1(1235.36,1523.56) 1(1235.36,1523.56) 1(1235.36,1697.96) 1(1235.36,1697.96) 1(1235.48,1523.48) 1(1235.48,1523.48) 1(1235.48,1697.92) 1(1235.48,1697.92) 1(1242.96,1515.96) 1(1242.96,1515.96) 1(1242.96,2008) 1(1242.96,2008) 1(1279.42,806.53) 1(1279.42,806.53) 1(1286.95,799) 1(1287.79,799) 1(1287.79,799) 1(1287.79,949) 1(1295.32,806.53) 1(1295.32,806.53) 1(1305.8,-2261) 1(1305.8,-2261) 1(1305.8,-1761) 1(1305.8,-1761) 1(1393.79,666.53) 1(1429.44,666.53) 1(1429.44,666.53) 1(1441.42,603) 1(1449.97,646) 1(1450.86,593.55) 1(1450.86,593.55) 1(1465.42,593.55) 1(1475.1,-1440.77) 1(1475.1,-1413.68) 1(1475.1,-1413.68) 1(1482.32,-1406.47) 1(1539.32,-1492.47) 1(1539.32,-1477.47) 1(1539.32,-1477.47) 1(1550.32,-1466.47) 1(1550.32,-1466.47) 1(1550.32,-1420.47) 1(1550.32,-1420.47) 1(1572.32,-1398.47) 1(1702.32,237.53) 1(1715.32,237.53) 1(1715.32,237.53) 1(1730.32,566.53) 1(1741.32,263.53) 1(1741.32,566.53) 1(1787.32,221.38) 1(1795.19,229.25) 1(1795.19,229.25) 1(1832.04,229.25) 1(1832.04,229.25) 1(1834.42,467) 1(1844.38,457.03) 1(1844.38,457.03) 1(1845.73,242.94) 1(1845.73,242.94) 1(1854.82,457.03) 1(1854.82,457.03) 1(1858.73,242.94) 1(1858.73,242.94) 1(1860.32,387.53) 1(1870.32,387.53) 1(1870.32,387.53) 1(1871.32,440.53) 1(1871.32,440.53) 1(1876.32,260.53) 1(1876.32,260.53) 1(1876.32,285.53) 1(1882.55,-76.95) 1(1892.32,419.53) 1(1898.32,359.53) 1(1916.55,-76.95) 1(1953.15,-254.95) 1(1953.15,-254.95) 1(1953.15,-223.46) 1(1953.15,-223.46) 1(1953.15,-219.95) 1(1953.15,-219.95) 1(1953.15,-188.46) 1(1953.15,-188.46) 1(1966.32,624.53) 1(1969.22,-384.47) 1(1969.22,-370.5) 1(1973.32,617.53) 1(1973.32,617.53) 1(1973.67,-254.95) 1(1973.67,-223.46) 1(1973.67,-219.95) 1(1973.67,-188.46) 1(1991.67,-254.95) 1(1991.67,-223.46) 1(1991.67,-219.95) 1(1991.67,-188.46) 1(2012.2,-254.95) 1(2012.2,-254.95) 1(2012.2,-223.46) 1(2012.2,-223.46) 1(2012.2,-219.95) 1(2012.2,-219.95) 1(2012.2,-188.46) 1(2012.2,-188.46) 1(2012.32,617.53) 1(2137.32,1001.53) 1(2144.32,1008.53) 1(2144.32,1008.53) 1(2150.32,1008.53) 1(2173.04,681.52) 1(2173.04,681.52) 1(2173.04,702.05) 1(2173.04,720.05) 1(2173.04,740.57) 1(2173.04,740.57) 1(2204.53,681.52) 1(2204.53,681.52) 1(2204.53,702.05) 1(2204.53,720.05) 1(2204.53,740.57) 1(2204.53,740.57) 1(2205.8,-2261) 1(2205.8,-2261) 1(2205.8,-1761) 1(2205.8,-1761) 1(2253.32,-319.47) 1(2253.32,-139.47) 1(2253.32,-139.47) 1(2271.32,-121.47) 1(2271.32,-121.47) 1(2273.33,-339.48) 1(2312.32,2156.53) 1(2314.32,-78.47) 1(2314.32,-69.47) 1(2317.22,-382.6) 1(2322.32,-377.47) 1(2322.32,-377.47) 1(2324.32,2156.53) 1(2324.32,2156.53) 1(2332.32,2148.53) 1(2360.92,-377.47) 1(2362.32,-50.47) 1(2383.32,-50.47) 1(2383.32,-50.47) 1(2395.32,-62.47) 1(2444.32,-121.47) 1(2444.32,-121.47) 1(2447.3,-339.48) 1(2447.3,-339.48) 1(2447.32,-1146.47) 1(2447.32,-1146.47) 1(2447.32,-940.47) 1(2447.32,-940.47) 1(2452.92,-100.07) 1(2462.32,-1161.47) 1(2462.32,-1161.47) 1(2463.32,-323.47) 1(2463.32,-323.47) 1(2463.32,-140.47) 1(2463.32,-140.47) 1(2465.32,-922.47) 1(2465.32,-922.47) 1(2520.92,-100.07) 1(2576.43,-881.47) 1(2588.32,344.53) 1(2588.32,344.53) 1(2588.32,374.53) 1(2611.82,321.03) 1(2628.88,306.25) 1(2628.88,306.25) 1(2628.88,337.75) 1(2628.88,337.75) 1(2640.21,-881.47) 1(2649.41,306.25) 1(2649.41,337.75) 1(2665.32,-922.47) 1(2665.32,-922.47) 1(2667.41,306.25) 1(2667.41,337.75) 1(2671.32,-1161.47) 1(2671.32,-1161.47) 1(2683.32,-1149.47) 1(2683.32,-1149.47) 1(2683.32,-940.47) 1(2683.32,-940.47) 1(2687.94,306.25) 1(2687.94,306.25) 1(2687.94,337.75) 1(2687.94,337.75)
  round 3.9 on Mech16: 1(447.25,-2012.48) 1(447.25,-1951.42) 1(447.25,-1814.73) 1(447.25,-1753.67) 1(447.25,-1614.87) 1(447.25,-1553.81) 1(508.32,-2012.48) 1(508.32,-1951.42) 1(508.32,-1814.73) 1(508.32,-1753.67) 1(508.32,-1614.87) 1(508.32,-1553.81) 1(589.51,-173.71) 1(589.51,-151.23) 1(589.51,-115.45) 1(589.51,-92.97) 1(597.43,-173.71) 1(597.43,-151.23) 1(597.43,-115.45) 1(597.43,-92.97) 1(603.88,-1734.53) 1(603.88,-1673.47) 1(609.2,-173.71) 1(609.2,-151.23) 1(609.2,-115.45) 1(609.2,-92.97) 1(617.11,-173.71) 1(617.11,-151.23) 1(617.11,-115.45) 1(617.11,-92.97) 1(628.88,-173.71) 1(628.88,-151.23) 1(628.88,-115.45) 1(628.88,-92.97) 1(636.8,-173.71) 1(636.8,-151.23) 1(636.8,-115.45) 1(636.8,-92.97) 1(664.95,-1734.53) 1(664.95,-1673.47) 1(753.88,-1956.53) 1(753.88,-1895.47) 1(814.95,-1956.53) 1(814.95,-1895.47) 1(1096.51,493.06) 1(1096.51,520.66) 1(1096.51,593.45) 1(1096.51,621.05) 1(1114.27,493.06) 1(1114.27,520.66) 1(1114.27,593.45) 1(1114.27,621.05) 1(1133.92,493.06) 1(1133.92,520.66) 1(1133.92,593.45) 1(1133.92,621.05) 1(1144.51,-1005.53) 1(1144.51,-944.47) 1(1151.67,493.06) 1(1151.67,520.66) 1(1151.67,593.45) 1(1151.67,621.05) 1(1171.32,493.06) 1(1171.32,520.66) 1(1171.32,593.45) 1(1171.32,621.05) 1(1189.07,493.06) 1(1189.07,520.66) 1(1189.07,593.45) 1(1189.07,621.05) 1(1205.58,-1005.53) 1(1205.58,-944.47) 1(1413.88,-1739.53) 1(1413.88,-1678.47) 1(1474.95,-1739.53) 1(1474.95,-1678.47) 1(2096.92,-241.95) 1(2096.92,-219.86) 1(2138.25,-1422.48) 1(2138.25,-1361.42) 1(2181.21,-241.95) 1(2181.21,-219.86) 1(2199.32,-1422.48) 1(2199.32,-1361.42) 1(2243.25,-1667.48) 1(2243.25,-1606.42) 1(2304.32,-1667.48) 1(2304.32,-1606.42)
  round 15.75 on Mech16: 1(632.84,-146.14)
  round 157.48 on Mech16: 1(648.79,1618.05) 1(648.79,2366.08) 1(648.79,2684.76) 1(2577.92,1618.05) 1(2577.92,2366.08) 1(2577.92,2684.76)
  round 23.98 on Mech16: 1(733.32,318.51)
  round 19.68 on Mech16: 1(770.13,-129.57) 1(937.67,44.29) 1(944.67,194.34) 1(1021.41,-281.6) 1(1025.41,-100.6) 1(1250.79,-314.35) 1(1639.82,-302.08) 1(2494.92,-365.51)
  round 51 on Mech16: 1(867.92,1715.94) 1(867.92,2443.94) 1(2159.42,1715.94) 1(2159.42,2443.94)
